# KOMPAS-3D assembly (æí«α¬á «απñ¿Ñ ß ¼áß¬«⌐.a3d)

Referenced files in D:\МОДЕЛЬ ТАНКА Т90\ДЕТАЛИ\БАШНЯ\башня сварная\: маска орудия.m3d, ствол.m3d, кожух ствола.m3d
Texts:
  Сборка орудие с маской
  stalker61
